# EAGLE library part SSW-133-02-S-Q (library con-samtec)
THROUGH-HOLE .025" SQ POST SOCKET Source: Samtec SSW.pdf
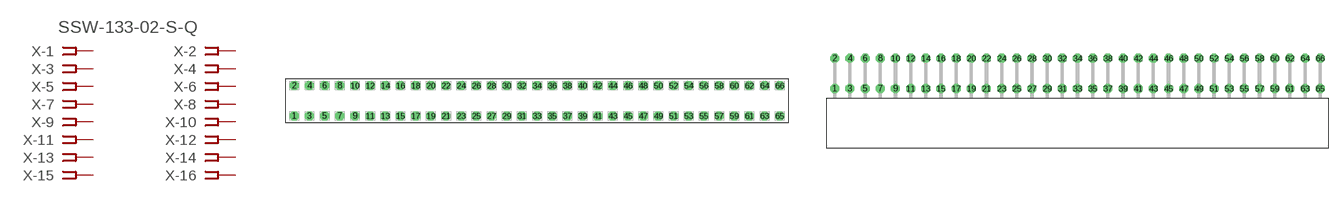
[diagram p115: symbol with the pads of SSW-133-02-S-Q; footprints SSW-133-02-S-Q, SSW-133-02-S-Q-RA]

Designator prefix X; gates -1=FPINV -2=FPIN -3=FPIN -4=FPIN -5=FPIN -6=FPIN -7=FPIN -8=FPIN -9=FPIN -10=FPIN -11=FPIN -12=FPIN -13=FPIN -14=FPIN -15=FPIN -16=FPIN -17=FPIN -18=FPIN -19=FPIN -20=FPIN -21=FPIN -22=FPIN -23=FPIN -24=FPIN -25=FPIN -26=FPIN -27=FPIN -28=FPIN -29=FPIN -30=FPIN -31=FPIN -32=FPIN -33=FPIN -34=FPIN -35=FPIN -36=FPIN -37=FPIN -38=FPIN -39=FPIN -40=FPIN -41=FPIN -42=FPIN -43=FPIN -44=FPIN -45=FPIN -46=FPIN -47=FPIN -48=FPIN -49=FPIN -50=FPIN -51=FPIN -52=FPIN -53=FPIN -54=FPIN -55=FPIN -56=FPIN -57=FPIN -58=FPIN -59=FPIN -60=FPIN -61=FPIN -62=FPIN -63=FPIN -64=FPIN -65=FPIN -66=FPIN

## SSW-133-02-S-Q (OC_FARNELL: unknown; OC_NEWARK: unknown)  [SSW-133-02-S-Q]
1  -1:1  pas
2  -2:1  pas
3  -3:1  pas
4  -4:1  pas
5  -5:1  pas
6  -6:1  pas
7  -7:1  pas
8  -8:1  pas
9  -9:1  pas
10  -10:1  pas
11  -11:1  pas
12  -12:1  pas
13  -13:1  pas
14  -14:1  pas
15  -15:1  pas
16  -16:1  pas
17  -17:1  pas
18  -18:1  pas
19  -19:1  pas
20  -20:1  pas
21  -21:1  pas
22  -22:1  pas
23  -23:1  pas
24  -24:1  pas
25  -25:1  pas
26  -26:1  pas
27  -27:1  pas
28  -28:1  pas
29  -29:1  pas
30  -30:1  pas
31  -31:1  pas
32  -32:1  pas
33  -33:1  pas
34  -34:1  pas
35  -35:1  pas
36  -36:1  pas
37  -37:1  pas
38  -38:1  pas
39  -39:1  pas
40  -40:1  pas
41  -41:1  pas
42  -42:1  pas
43  -43:1  pas
44  -44:1  pas
45  -45:1  pas
46  -46:1  pas
47  -47:1  pas
48  -48:1  pas
49  -49:1  pas
50  -50:1  pas
51  -51:1  pas
52  -52:1  pas
53  -53:1  pas
54  -54:1  pas
55  -55:1  pas
56  -56:1  pas
57  -57:1  pas
58  -58:1  pas
59  -59:1  pas
60  -60:1  pas
61  -61:1  pas
62  -62:1  pas
63  -63:1  pas
64  -64:1  pas
65  -65:1  pas
66  -66:1  pas

## SSW-133-02-S-QRA (OC_FARNELL: unknown; OC_NEWARK: unknown)  [SSW-133-02-S-Q-RA]
Pads as for SSW-133-02-S-Q

## Footprint SSW-133-02-S-Q (pad centres in mm)
THROUGH-HOLE .025" SQ POST SOCKET Source: Samtec SSW.pdf
drill 1 pad 1.5 octagon: 1 -40.64,-2.54; 2 -40.64,2.54; 3 -38.1,-2.54; 4 -38.1,2.54; 5 -35.56,-2.54; 6 -35.56,2.54; 7 -33.02,-2.54; 8 -33.02,2.54; 9 -30.48,-2.54; 10 -30.48,2.54; 11 -27.94,-2.54; 12 -27.94,2.54; 13 -25.4,-2.54; 14 -25.4,2.54; 15 -22.86,-2.54; 16 -22.86,2.54; 17 -20.32,-2.54; 18 -20.32,2.54; 19 -17.78,-2.54; 20 -17.78,2.54; 21 -15.24,-2.54; 22 -15.24,2.54; 23 -12.7,-2.54; 24 -12.7,2.54; 25 -10.16,-2.54; 26 -10.16,2.54; 27 -7.62,-2.54; 28 -7.62,2.54; 29 -5.08,-2.54; 30 -5.08,2.54; 31 -2.54,-2.54; 32 -2.54,2.54; 33 0,-2.54; 34 0,2.54; 35 2.54,-2.54; 36 2.54,2.54; 37 5.08,-2.54; 38 5.08,2.54; 39 7.62,-2.54; 40 7.62,2.54; 41 10.16,-2.54; 42 10.16,2.54; 43 12.7,-2.54; 44 12.7,2.54; 45 15.24,-2.54; 46 15.24,2.54; 47 17.78,-2.54; 48 17.78,2.54; 49 20.32,-2.54; 50 20.32,2.54; 51 22.86,-2.54; 52 22.86,2.54; 53 25.4,-2.54; 54 25.4,2.54; 55 27.94,-2.54; 56 27.94,2.54; 57 30.48,-2.54; 58 30.48,2.54; 59 33.02,-2.54; 60 33.02,2.54; 61 35.56,-2.54; 62 35.56,2.54; 63 38.1,-2.54; 64 38.1,2.54; 65 40.64,-2.54; 66 40.64,2.54

## Footprint SSW-133-02-S-Q-RA (pad centres in mm)
THROUGH-HOLE .025" SQ POST SOCKET Source: Samtec SSW.pdf
drill 1 pad 1.5 octagon: 1 -40.64,1.524; 2 -40.64,6.604; 3 -38.1,1.524; 4 -38.1,6.604; 5 -35.56,1.524; 6 -35.56,6.604; 7 -33.02,1.524; 8 -33.02,6.604; 9 -30.48,1.524; 10 -30.48,6.604; 11 -27.94,1.524; 12 -27.94,6.604; 13 -25.4,1.524; 14 -25.4,6.604; 15 -22.86,1.524; 16 -22.86,6.604; 17 -20.32,1.524; 18 -20.32,6.604; 19 -17.78,1.524; 20 -17.78,6.604; 21 -15.24,1.524; 22 -15.24,6.604; 23 -12.7,1.524; 24 -12.7,6.604; 25 -10.16,1.524; 26 -10.16,6.604; 27 -7.62,1.524; 28 -7.62,6.604; 29 -5.08,1.524; 30 -5.08,6.604; 31 -2.54,1.524; 32 -2.54,6.604; 33 0,1.524; 34 0,6.604; 35 2.54,1.524; 36 2.54,6.604; 37 5.08,1.524; 38 5.08,6.604; 39 7.62,1.524; 40 7.62,6.604; 41 10.16,1.524; 42 10.16,6.604; 43 12.7,1.524; 44 12.7,6.604; 45 15.24,1.524; 46 15.24,6.604; 47 17.78,1.524; 48 17.78,6.604; 49 20.32,1.524; 50 20.32,6.604; 51 22.86,1.524; 52 22.86,6.604; 53 25.4,1.524; 54 25.4,6.604; 55 27.94,1.524; 56 27.94,6.604; 57 30.48,1.524; 58 30.48,6.604; 59 33.02,1.524; 60 33.02,6.604; 61 35.56,1.524; 62 35.56,6.604; 63 38.1,1.524; 64 38.1,6.604; 65 40.64,1.524; 66 40.64,6.604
